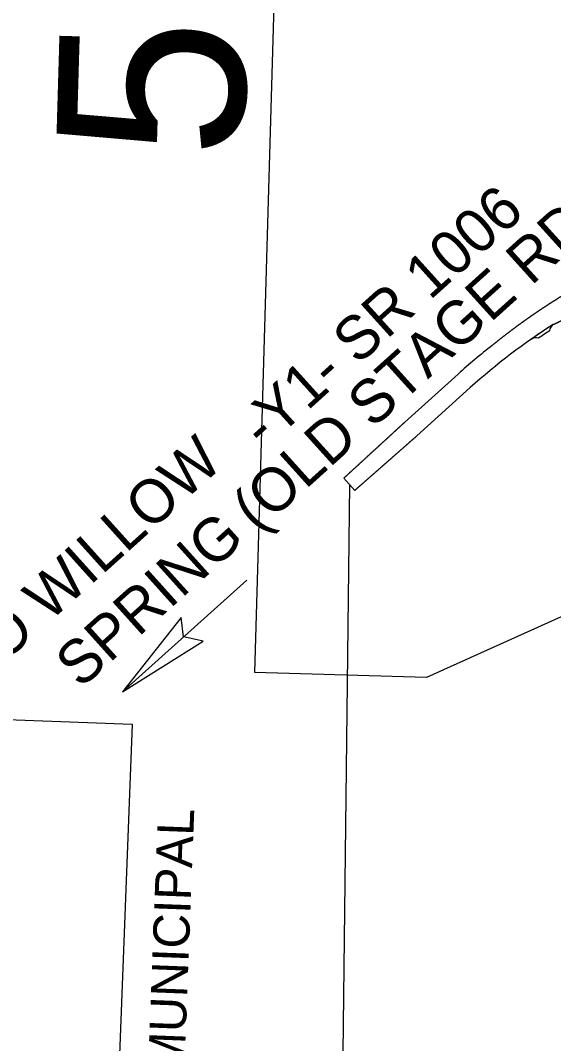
# Model space of a CAD drawing. Extents: x 2094564 to 2100382, y 679033 to 692366.
# Drawn here: x 2096747 to 2097390, y 684877 to 686113 of the extents above; entities that cross this region are included whole.
import ezdxf

# ---------------------------------------------------------------- set-up
doc = ezdxf.new("R2010")
doc.units = 0
for name, color, linetype in [('Exist Horizontal Alignment', 7, 'Continuous'), ('Pattern 17', 7, 'Continuous'), ('Prop Horizontal Alignment', 7, 'Continuous'), ('Prop Horizontal Alignment Direction Label', 7, 'Continuous'), ('Prop Shade Light', 7, 'Continuous'), ('Scratch_Level_0', 7, 'Continuous')]:
    doc.layers.add(name, color=color, linetype=linetype)

msp = doc.modelspace()

# ---------------------------------------------------------------- linework, layer by layer
at = {"layer": 'Exist Horizontal Alignment'}
msp.add_lwpolyline([(2096940.4, 685391.7), (2096869.9, 685302), (2096967.3, 685362.9), (2096943.2, 685368.1)], close=True, dxfattribs=at)
at = {"layer": 'Pattern 17'}
for points in [[(2098090.8, 685704.4), (2097236.9, 685319), (2097029.4, 685325), (2097061.3, 686424.4), (2097067.1, 686624.4), (2097093.4, 686623.6), (2097228.1, 686619.7), (2097231.4, 686733), (2098120, 686707.2)], [(2096614.3, 683367.4), (2096687.2, 685270), (2096881.4, 685262.6), (2096808.4, 683360)]]:
    msp.add_lwpolyline(points, close=True, dxfattribs=at)
at = {"layer": 'Prop Horizontal Alignment'}
msp.add_line((2096869.9, 685302), (2097019.8, 685436.7), dxfattribs=at)
at = {"layer": 'Prop Shade Light'}
for p, q in [((2097274.9, 685685.9), (2097210.5, 685627.7)), ((2097225.2, 685611.4), (2097289.6, 685669.5)), ((2097136.9, 685560), (2097150.1, 685545.3))]:
    msp.add_line(p, q, dxfattribs=at)
msp.add_lwpolyline([(2097363, 685727.9), (2097363.1, 685727.9)], dxfattribs=at)
for centre, radius, start, end in [((2097791.5, 685113.6), 749, 122.4115, 132.076), ((2097791.5, 685113.6), 749, 122.4351, 124.8967), ((2097795.3, 685116.2), 745, 123.3982, 124.6288), ((2097395.2, 685737.3), 10, 122.4351, 175.1032), ((2097368.8, 685719.7), 10, 71.8069, 125.2465), ((2097791.5, 685113.6), 771, 128.0657, 132.076)]:
    msp.add_arc(centre, radius, start, end, dxfattribs=at)
for points in [[(2097389.3, 685773.4), (2097388.8, 685773.1), (2097388, 685772.6), (2097387.3, 685772.1), (2097386.5, 685771.6), (2097385.7, 685771.1), (2097385, 685770.6), (2097384.2, 685770.1), (2097383.4, 685769.6), (2097382.7, 685769.1), (2097381.9, 685768.6), (2097381.1, 685768.1), (2097380.4, 685767.6), (2097379.6, 685767.1), (2097378.8, 685766.6), (2097378.1, 685766.1), (2097377.3, 685765.6), (2097376.5, 685765.1), (2097375.8, 685764.6), (2097375, 685764.1), (2097374.3, 685763.6), (2097373.5, 685763.1), (2097372.7, 685762.6), (2097372, 685762.1), (2097371.2, 685761.5), (2097370.5, 685761)], [(2097408.6, 685785.3), (2097408.3, 685785.1), (2097407.5, 685784.7), (2097406.7, 685784.2), (2097406, 685783.7), (2097405.2, 685783.3), (2097404.4, 685782.8), (2097403.6, 685782.3), (2097402.8, 685781.8), (2097402, 685781.4), (2097401.3, 685780.9), (2097400.5, 685780.4), (2097399.7, 685779.9), (2097398.9, 685779.4), (2097398.1, 685779), (2097397.4, 685778.5), (2097396.6, 685778), (2097395.8, 685777.5), (2097395, 685777), (2097394.2, 685776.5), (2097393.5, 685776), (2097392.7, 685775.6), (2097391.9, 685775.1), (2097391.1, 685774.6), (2097390.4, 685774.1), (2097389.6, 685773.6), (2097389.3, 685773.4)], [(2097370.5, 685761), (2097369.7, 685760.5), (2097368.9, 685760), (2097368.2, 685759.5), (2097367.4, 685759), (2097366.7, 685758.4), (2097365.9, 685757.9), (2097365.2, 685757.4), (2097364.4, 685756.9), (2097363.7, 685756.4), (2097362.9, 685755.8), (2097362.2, 685755.3), (2097361.4, 685754.8), (2097360.7, 685754.3), (2097359.9, 685753.7), (2097359.2, 685753.2), (2097358.4, 685752.7), (2097357.7, 685752.2), (2097356.9, 685751.6), (2097356.2, 685751.1), (2097355.4, 685750.6), (2097354.7, 685750), (2097353.9, 685749.5), (2097353.2, 685749), (2097352.5, 685748.4), (2097352, 685748.1)], [(2097390.1, 685745.9), (2097390.7, 685746.2), (2097391.3, 685746.5), (2097391.9, 685746.8), (2097392.5, 685747.1), (2097393.1, 685747.4), (2097393.7, 685747.7), (2097394.3, 685747.9), (2097394.9, 685748.2), (2097395.5, 685748.5), (2097396.1, 685748.8), (2097396.7, 685749.1), (2097397.3, 685749.4), (2097397.9, 685749.7), (2097398.5, 685750), (2097399.1, 685750.3), (2097399.7, 685750.5), (2097400.4, 685750.8), (2097401, 685751.1), (2097401.6, 685751.4), (2097402.2, 685751.7), (2097402.8, 685752), (2097403.4, 685752.2), (2097404, 685752.5), (2097404.6, 685752.8), (2097405, 685753)], [(2097352, 685748.1), (2097351.7, 685747.9), (2097351, 685747.4), (2097350.2, 685746.8), (2097349.5, 685746.3), (2097348.8, 685745.7), (2097348, 685745.2), (2097347.3, 685744.7), (2097346.5, 685744.1), (2097345.8, 685743.6), (2097345.1, 685743), (2097344.3, 685742.5), (2097343.6, 685741.9), (2097342.9, 685741.4), (2097342.1, 685740.8), (2097341.4, 685740.3), (2097340.7, 685739.8), (2097339.9, 685739.2), (2097339.2, 685738.7), (2097338.5, 685738.1), (2097337.7, 685737.5), (2097337, 685737), (2097336.3, 685736.4), (2097335.6, 685735.9), (2097334.8, 685735.3), (2097334.1, 685734.8), (2097333.9, 685734.6)], [(2097333.9, 685734.6), (2097333.4, 685734.2), (2097332.7, 685733.7), (2097331.9, 685733.1), (2097331.2, 685732.5), (2097330.5, 685732), (2097329.8, 685731.4), (2097329, 685730.9), (2097328.3, 685730.3), (2097327.6, 685729.7), (2097326.9, 685729.2), (2097326.2, 685728.6), (2097325.4, 685728), (2097324.7, 685727.5), (2097324, 685726.9), (2097323.3, 685726.3), (2097322.6, 685725.8), (2097321.9, 685725.2), (2097321.2, 685724.6), (2097320.4, 685724), (2097319.7, 685723.5), (2097319, 685722.9), (2097318.3, 685722.3), (2097317.6, 685721.7), (2097316.9, 685721.2), (2097316.2, 685720.6)], [(2097210.5, 685627.7), (2097210, 685627.2), (2097209.5, 685626.8), (2097209, 685626.3), (2097208.5, 685625.9), (2097208, 685625.4), (2097207.5, 685624.9), (2097207, 685624.5), (2097206.5, 685624), (2097206, 685623.6), (2097205.5, 685623.1), (2097205, 685622.7), (2097204.5, 685622.2), (2097204, 685621.7), (2097203.5, 685621.3), (2097203, 685620.8), (2097202.5, 685620.4), (2097202, 685619.9), (2097201.5, 685619.5), (2097201, 685619), (2097200.5, 685618.5), (2097200, 685618.1), (2097199.5, 685617.6), (2097199, 685617.2), (2097198.5, 685616.7), (2097198.2, 685616.4)], [(2097198.2, 685616.4), (2097198, 685616.2), (2097197.5, 685615.8), (2097197, 685615.3), (2097196.5, 685614.9), (2097196, 685614.4), (2097195.5, 685614), (2097195.1, 685613.5), (2097194.6, 685613), (2097194.1, 685612.6), (2097193.6, 685612.1), (2097193.1, 685611.7), (2097192.6, 685611.2), (2097192.1, 685610.8), (2097191.6, 685610.3), (2097191.1, 685609.8), (2097190.6, 685609.4), (2097190.1, 685608.9), (2097189.6, 685608.5), (2097189.1, 685608), (2097188.6, 685607.6), (2097188.1, 685607.1), (2097187.6, 685606.6), (2097187.1, 685606.2), (2097186.6, 685605.7), (2097186.1, 685605.3), (2097185.9, 685605.1)], [(2097185.9, 685605.1), (2097185.6, 685604.8), (2097185.1, 685604.3), (2097184.6, 685603.9), (2097184.1, 685603.4), (2097183.6, 685603), (2097183.1, 685602.5), (2097182.6, 685602.1), (2097182.1, 685601.6), (2097181.6, 685601.1), (2097181.1, 685600.7), (2097180.6, 685600.2), (2097180.1, 685599.8), (2097179.6, 685599.3), (2097179.1, 685598.9), (2097178.6, 685598.4), (2097178.2, 685597.9), (2097177.7, 685597.5), (2097177.2, 685597), (2097176.7, 685596.6), (2097176.2, 685596.1), (2097175.7, 685595.7), (2097175.2, 685595.2), (2097174.7, 685594.7), (2097174.2, 685594.3), (2097173.7, 685593.8)], [(2097200.2, 685589.3), (2097200.4, 685589.5), (2097200.9, 685589.9), (2097201.4, 685590.4), (2097201.9, 685590.8), (2097202.4, 685591.3), (2097202.9, 685591.7), (2097203.4, 685592.2), (2097203.9, 685592.6), (2097204.4, 685593), (2097204.9, 685593.5), (2097205.4, 685593.9), (2097205.9, 685594.4), (2097206.4, 685594.8), (2097206.9, 685595.3), (2097207.5, 685595.7), (2097208, 685596.2), (2097208.5, 685596.6), (2097209, 685597.1), (2097209.5, 685597.5), (2097210, 685598), (2097210.5, 685598.4), (2097211, 685598.9), (2097211.5, 685599.3), (2097212, 685599.7), (2097212.5, 685600.2), (2097212.7, 685600.3)], [(2097212.7, 685600.3), (2097213, 685600.6), (2097213.5, 685601.1), (2097214, 685601.5), (2097214.6, 685602), (2097215.1, 685602.4), (2097215.6, 685602.9), (2097216.1, 685603.3), (2097216.6, 685603.8), (2097217.1, 685604.2), (2097217.6, 685604.7), (2097218.1, 685605.1), (2097218.6, 685605.6), (2097219.1, 685606), (2097219.6, 685606.4), (2097220.1, 685606.9), (2097220.6, 685607.3), (2097221.1, 685607.8), (2097221.7, 685608.2), (2097222.2, 685608.7), (2097222.7, 685609.1), (2097223.2, 685609.6), (2097223.7, 685610), (2097224.2, 685610.5), (2097225.2, 685611.4)], [(2097173.7, 685593.8), (2097173.2, 685593.4), (2097172.7, 685592.9), (2097172.2, 685592.5), (2097171.7, 685592), (2097171.2, 685591.5), (2097170.7, 685591.1), (2097170.2, 685590.6), (2097169.7, 685590.2), (2097169.2, 685589.7), (2097168.7, 685589.3), (2097168.2, 685588.8), (2097167.7, 685588.3), (2097167.2, 685587.9), (2097166.7, 685587.4), (2097166.2, 685587), (2097165.7, 685586.5), (2097165.2, 685586.1), (2097164.7, 685585.6), (2097164.2, 685585.1), (2097163.7, 685584.7), (2097163.2, 685584.2), (2097162.7, 685583.8), (2097162.2, 685583.3), (2097161.7, 685582.8), (2097161.4, 685582.5)], [(2097187.7, 685578.3), (2097188.2, 685578.8), (2097188.7, 685579.2), (2097189.2, 685579.7), (2097189.7, 685580.1), (2097190.2, 685580.5), (2097190.7, 685581), (2097191.2, 685581.4), (2097191.7, 685581.9), (2097192.2, 685582.3), (2097192.7, 685582.8), (2097193.2, 685583.2), (2097193.8, 685583.7), (2097194.3, 685584.1), (2097194.8, 685584.6), (2097195.3, 685585), (2097195.8, 685585.5), (2097196.3, 685585.9), (2097196.8, 685586.3), (2097197.3, 685586.8), (2097197.8, 685587.2), (2097198.3, 685587.7), (2097198.8, 685588.1), (2097199.3, 685588.6), (2097199.8, 685589), (2097200.2, 685589.3)], [(2097161.4, 685582.5), (2097161.2, 685582.4), (2097160.8, 685581.9), (2097160.3, 685581.5), (2097159.8, 685581), (2097159.3, 685580.6), (2097158.8, 685580.1), (2097158.3, 685579.6), (2097157.8, 685579.2), (2097157.3, 685578.7), (2097156.8, 685578.3), (2097156.3, 685577.8), (2097155.8, 685577.4), (2097155.3, 685576.9), (2097154.8, 685576.4), (2097154.3, 685576), (2097153.8, 685575.5), (2097153.3, 685575.1), (2097152.8, 685574.6), (2097152.3, 685574.2), (2097151.8, 685573.7), (2097151.3, 685573.2), (2097150.8, 685572.8), (2097150.3, 685572.3), (2097149.8, 685571.9), (2097149.3, 685571.4), (2097149.1, 685571.3)], [(2097175.1, 685567.3), (2097175.5, 685567.6), (2097176, 685568), (2097176.5, 685568.5), (2097177, 685568.9), (2097177.5, 685569.4), (2097178, 685569.8), (2097178.5, 685570.3), (2097179, 685570.7), (2097179.5, 685571.2), (2097180.1, 685571.6), (2097180.6, 685572.1), (2097181.1, 685572.5), (2097181.6, 685573), (2097182.1, 685573.4), (2097182.6, 685573.8), (2097183.1, 685574.3), (2097183.6, 685574.7), (2097184.1, 685575.2), (2097184.6, 685575.6), (2097185.1, 685576.1), (2097185.6, 685576.5), (2097186.1, 685577), (2097186.7, 685577.4), (2097187.2, 685577.9), (2097187.7, 685578.3)], [(2097149.1, 685571.3), (2097148.8, 685571), (2097148.3, 685570.5), (2097147.8, 685570), (2097147.3, 685569.6), (2097146.8, 685569.1), (2097146.3, 685568.7), (2097145.8, 685568.2), (2097145.3, 685567.8), (2097144.8, 685567.3), (2097144.3, 685566.8), (2097143.8, 685566.4), (2097143.3, 685565.9), (2097142.8, 685565.5), (2097142.3, 685565), (2097141.8, 685564.6), (2097141.4, 685564.1), (2097140.9, 685563.6), (2097140.4, 685563.2), (2097139.9, 685562.7), (2097139.4, 685562.3), (2097138.9, 685561.8), (2097138.4, 685561.4), (2097137.9, 685560.9), (2097136.9, 685560)], [(2097162.6, 685556.3), (2097162.8, 685556.4), (2097163.3, 685556.9), (2097163.8, 685557.3), (2097164.3, 685557.8), (2097164.8, 685558.2), (2097165.3, 685558.7), (2097165.8, 685559.1), (2097166.4, 685559.6), (2097166.9, 685560), (2097167.4, 685560.5), (2097167.9, 685560.9), (2097168.4, 685561.4), (2097168.9, 685561.8), (2097169.4, 685562.2), (2097169.9, 685562.7), (2097170.4, 685563.1), (2097170.9, 685563.6), (2097171.4, 685564), (2097171.9, 685564.5), (2097172.4, 685564.9), (2097173, 685565.4), (2097173.5, 685565.8), (2097174, 685566.3), (2097174.5, 685566.7), (2097175, 685567.2), (2097175.1, 685567.3)], [(2097150.1, 685545.3), (2097150.6, 685545.7), (2097151.1, 685546.2), (2097151.6, 685546.6), (2097152.1, 685547.1), (2097152.6, 685547.5), (2097153.2, 685548), (2097153.7, 685548.4), (2097154.2, 685548.9), (2097154.7, 685549.3), (2097155.2, 685549.8), (2097155.7, 685550.2), (2097156.2, 685550.6), (2097156.7, 685551.1), (2097157.2, 685551.5), (2097157.7, 685552), (2097158.2, 685552.4), (2097158.7, 685552.9), (2097159.2, 685553.3), (2097159.8, 685553.8), (2097160.3, 685554.2), (2097160.8, 685554.7), (2097161.3, 685555.1), (2097161.8, 685555.6), (2097162.3, 685556), (2097162.6, 685556.3)]]:
    msp.add_spline(points, degree=3, dxfattribs=at)
at = {"layer": 'Scratch_Level_0'}
msp.add_line((2097143.6, 685552.6), (2097135.7, 684865.5), dxfattribs=at)

# ---------------------------------------------------------------- texts
at = {"layer": 'Prop Horizontal Alignment Direction Label'}
msp.add_text('5', height=225.9, rotation=88.3348, dxfattribs=at).set_placement((2097015.2, 685945))
at = {"layer": 'Scratch_Level_0'}
for s, height, rotation, p in [('(OLD STAGE RD.)', 52.563, 42.07, (2097032.5, 685493.4)), ('-Y1- SR 1006', 52.563, 42.07, (2097040.7, 685593.7)), ('TO WILLOW', 52.56, 41.9482, (2096693.8, 685306.9)), ('SPRING', 52.56, 41.9482, (2096819, 685304.6)), ('NOTE: THIS PROJECT DOES NOT FALL WITHIN ANY MUNICIPAL', 43.826, 87.8037, (2096887.7, 683367.2))]:
    msp.add_text(s, height=height, rotation=rotation, dxfattribs=at).set_placement(p)

doc.saveas('drawing.dxf')
